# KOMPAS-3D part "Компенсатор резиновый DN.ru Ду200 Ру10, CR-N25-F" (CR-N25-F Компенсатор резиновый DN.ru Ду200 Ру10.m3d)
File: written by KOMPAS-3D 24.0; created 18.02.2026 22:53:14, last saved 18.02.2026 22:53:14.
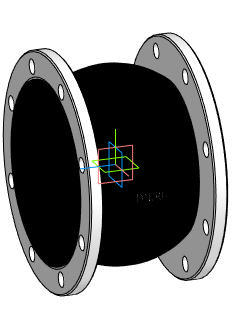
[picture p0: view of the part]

Document properties: Автор: DN.RU; Полное имя файла: D:\PROJECT CAD\DN.RU\...178(1)(ACTUALE). CR-N25-F Компенсатор резиновый DN.ru Ру10-16\DN200_PN10\CR-N25-F Компенсатор резиновый DN.ru Ду200 Ру10.m3d

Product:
- Body: Твердое тело2  | qty 1
    Масса: 47.364795
- Part/product: Компенсатор резиновый DN.ru Ду200 Ру10  | designation CR-N25-F
    Масса: 20
    Раздел спецификации: Прочие изделия
    Комментарий: D140-02397
    Примечание: D140-02397
    additional columns: Типовые

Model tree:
1. Твердое тело2  (labels: Твердое тело2)

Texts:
  CR-N25-F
